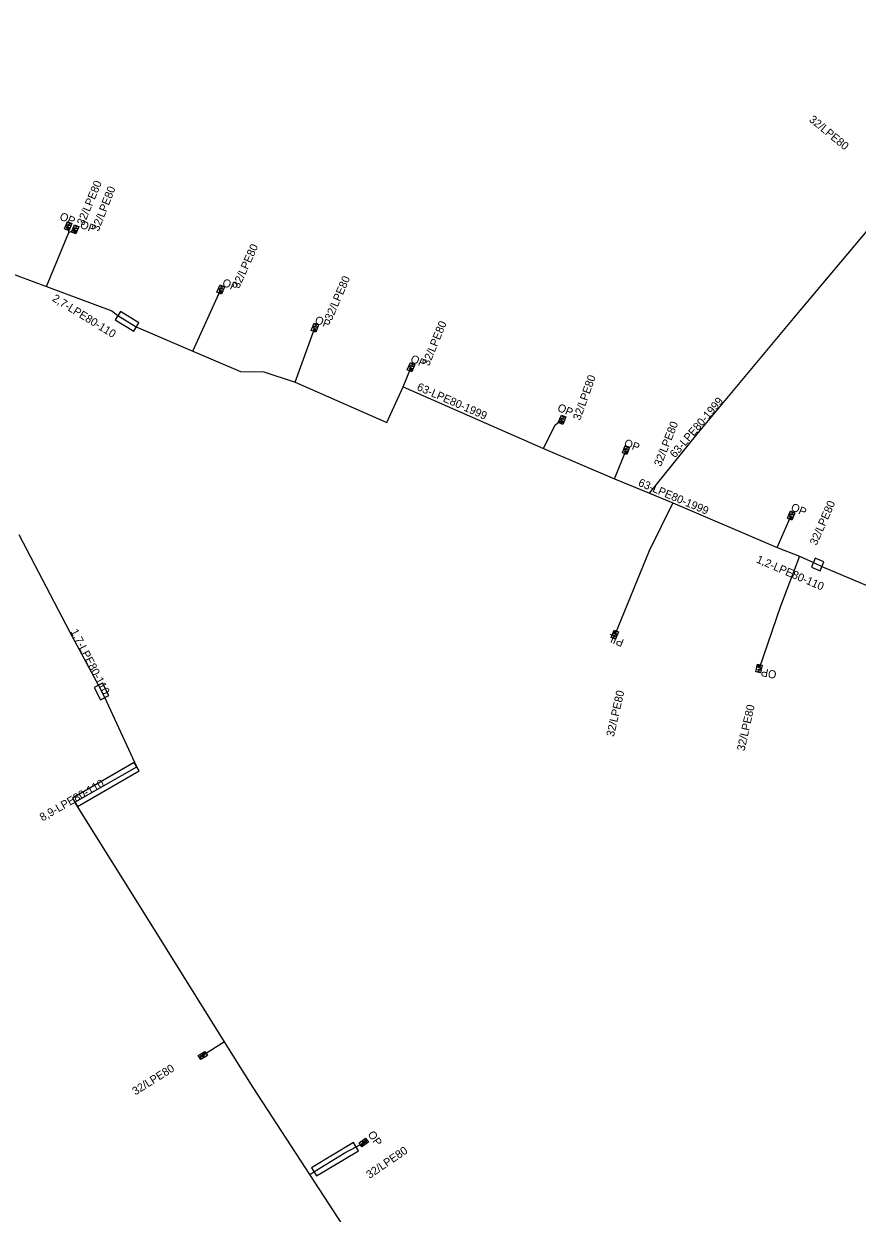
# Model space of a CAD drawing. Extents: x -762509 to -761250, y -1153000 to -1152256.
# Drawn here: x -761661 to -761556.9, y -1152409.7 to -1152261.2 of the extents above; entities that cross this region are included whole.
import ezdxf

# ---------------------------------------------------------------- set-up
doc = ezdxf.new("R2010")
doc.units = 0
for name, color, linetype in [('Vrstva 21', 7, 'Continuous'), ('Vrstva 29', 7, 'Continuous'), ('Vrstva 31', 7, 'Continuous'), ('Vrstva 32', 7, 'Continuous')]:
    doc.layers.add(name, color=color, linetype=linetype)

msp = doc.modelspace()

# ---------------------------------------------------------------- linework, layer by layer
at = {"layer": 'Vrstva 21'}
for points in [[(-761582.89, -1152319.81), (-761576.95, -1152312.47), (-761564.9, -1152298), (-761554.61, -1152285.76), (-761550.95, -1152281.56), (-761549.55, -1152279.71), (-761545.49, -1152275.05), (-761544.72, -1152274.11), (-761543.9, -1152273.16), (-761542.29, -1152270.99), (-761534.6, -1152261.85), (-761533.98, -1152261.17)], [(-761673.77, -1152305.98), (-761670.38, -1152302.71), (-761665.53, -1152296.98), (-761663.56, -1152291.99), (-761658.21, -1152293.99), (-761650.05, -1152297.02), (-761649.29, -1152297.62), (-761646.99, -1152299.04), (-761639.92, -1152302.07), (-761633.99, -1152304.61), (-761631.07, -1152304.65), (-761627.14, -1152305.92), (-761615.71, -1152310.97), (-761613.66, -1152306.5), (-761596.11, -1152314.22), (-761587.24, -1152318.01), (-761582.89, -1152319.81)], [(-761582.89, -1152319.81), (-761579.97, -1152321.01), (-761566.93, -1152326.59), (-761564.15, -1152327.67), (-761562.41, -1152328.48), (-761561.34, -1152328.94), (-761548.12, -1152334.52), (-761539.24, -1152337.93), (-761531.97, -1152340.58), (-761528.13, -1152341.92), (-761526.3, -1152342.45), (-761512.91, -1152346.54), (-761513.62, -1152349.91), (-761513.51, -1152352.59), (-761512.99, -1152352.67)], [(-761617.59, -1152416.73), (-761625.33, -1152404.89), (-761632.4, -1152394.03), (-761635.99, -1152388.35), (-761645.13, -1152373.62), (-761654.65, -1152358.4), (-761646.94, -1152353.98), (-761650.93, -1152345.33), (-761651.72, -1152343.79), (-761655.26, -1152337.2), (-761661.63, -1152325.02)]]:
    msp.add_lwpolyline(points, dxfattribs=at)
at = {"layer": 'Vrstva 29'}
for points in [[(-761649.61, -1152298.13), (-761647.31, -1152299.55), (-761646.67, -1152298.53), (-761648.97, -1152297.11)], [(-761562.65, -1152329.03), (-761561.58, -1152329.49), (-761561.1, -1152328.39), (-761562.17, -1152327.93)], [(-761652.25, -1152344.06), (-761651.46, -1152345.6), (-761650.4, -1152345.06), (-761651.19, -1152343.52)], [(-761654.35, -1152358.92), (-761646.64, -1152354.5), (-761647.24, -1152353.46), (-761654.95, -1152357.88)], [(-761624.49, -1152405.09), (-761619.23, -1152401.94), (-761619.85, -1152400.92), (-761625.11, -1152404.06)]]:
    msp.add_lwpolyline(points, close=True, dxfattribs=at)
at = {"layer": 'Vrstva 31'}
for points in [[(-761655.41, -1152287.23), (-761655.49, -1152286.45)], [(-761658.21, -1152293.99), (-761655.41, -1152287.24)], [(-761655.41, -1152287.24), (-761654.63, -1152286.85)], [(-761639.92, -1152302.07), (-761639.5, -1152301.15), (-761636.44, -1152294.37)], [(-761627.14, -1152305.92), (-761624.68, -1152299.13)], [(-761613.66, -1152306.5), (-761612.66, -1152304.06)], [(-761596.11, -1152314.22), (-761594.65, -1152311.27), (-761593.8, -1152310.63)], [(-761587.24, -1152318.01), (-761585.81, -1152314.41)], [(-761579.97, -1152321.01), (-761582.94, -1152327.01), (-761587.2, -1152337.48)], [(-761566.93, -1152326.59), (-761565.18, -1152322.59)], [(-761564.15, -1152327.67), (-761566.53, -1152333.91), (-761569.19, -1152341.7)], [(-761635.99, -1152388.35), (-761638.68, -1152390.04)], [(-761625.33, -1152404.89), (-761624.8, -1152404.58), (-761621.04, -1152402.25), (-761619.54, -1152401.43), (-761618.57, -1152400.92)]]:
    msp.add_lwpolyline(points, dxfattribs=at)
at = {"layer": 'Vrstva 32'}
for p, q in [((-761655.729, -1152286.567), (-761655.406, -1152286.703)), ((-761655.574, -1152286.199), (-761655.252, -1152286.335)), ((-761655.174, -1152286.149), (-761655.497, -1152286.014)), ((-761655.326, -1152286.085), (-761655.404, -1152286.271)), ((-761654.721, -1152286.601), (-761654.395, -1152286.729)), ((-761654.321, -1152286.542), (-761654.647, -1152286.414)), ((-761654.475, -1152286.482), (-761654.548, -1152286.669)), ((-761654.866, -1152286.973), (-761654.54, -1152287.101)), ((-761636.122, -1152294.07), (-761636.445, -1152293.933)), ((-761636.274, -1152294.005), (-761636.353, -1152294.19)), ((-761636.679, -1152294.485), (-761636.357, -1152294.622)), ((-761636.523, -1152294.118), (-761636.201, -1152294.255)), ((-761624.914, -1152299.257), (-761624.586, -1152299.379)), ((-761624.774, -1152298.883), (-761624.446, -1152299.005)), ((-761624.376, -1152298.817), (-761624.704, -1152298.695)), ((-761624.531, -1152298.759), (-761624.601, -1152298.947)), ((-761612.901, -1152304.173), (-761612.58, -1152304.314)), ((-761612.74, -1152303.808), (-761612.419, -1152303.949)), ((-761612.338, -1152303.765), (-761612.659, -1152303.624)), ((-761612.489, -1152303.698), (-761612.57, -1152303.882)), ((-761593.885, -1152310.379), (-761593.562, -1152310.513)), ((-761593.485, -1152310.328), (-761593.808, -1152310.193)), ((-761593.637, -1152310.264), (-761593.714, -1152310.45)), ((-761594.038, -1152310.748), (-761593.715, -1152310.882)), ((-761586.043, -1152314.538), (-761585.715, -1152314.658)), ((-761585.906, -1152314.163), (-761585.577, -1152314.284)), ((-761585.508, -1152314.095), (-761585.837, -1152313.975)), ((-761585.663, -1152314.038), (-761585.732, -1152314.227)), ((-761565.262, -1152322.337), (-761564.941, -1152322.477)), ((-761564.86, -1152322.293), (-761565.181, -1152322.153)), ((-761565.012, -1152322.227), (-761565.092, -1152322.411)), ((-761565.421, -1152322.703), (-761565.1, -1152322.843)), ((-761587.513, -1152337.785), (-761587.189, -1152337.917)), ((-761587.113, -1152337.731), (-761587.438, -1152337.599)), ((-761587.361, -1152337.847), (-761587.285, -1152337.661)), ((-761586.963, -1152337.361), (-761587.287, -1152337.229)), ((-761568.978, -1152341.539), (-761569.321, -1152341.469)), ((-761569.441, -1152342.057), (-761569.098, -1152342.127)), ((-761569.058, -1152341.93), (-761569.401, -1152341.86)), ((-761569.28, -1152342.09), (-761569.239, -1152341.893)), ((-761639.112, -1152390.104), (-761638.926, -1152390.401)), ((-761639.024, -1152390.244), (-761638.854, -1152390.137)), ((-761638.755, -1152390.294), (-761638.942, -1152389.997)), ((-761638.418, -1152390.081), (-761638.604, -1152389.785)), ((-761618.834, -1152400.894), (-761618.631, -1152401.179)), ((-761618.509, -1152400.662), (-761618.306, -1152400.947)), ((-761618.238, -1152400.696), (-761618.402, -1152400.813)), ((-761618.142, -1152400.83), (-761618.346, -1152400.545))]:
    msp.add_line(p, q, dxfattribs=at)
for points in [[(-761655.02, -1152286.105), (-761655.407, -1152287.028), (-761655.96, -1152286.795), (-761655.573, -1152285.873), (-761655.02, -1152286.105)], [(-761655.29, -1152286.426), (-761655.521, -1152286.329), (-761655.572, -1152286.323), (-761655.614, -1152286.339), (-761655.646, -1152286.371), (-761655.657, -1152286.397), (-761655.658, -1152286.443), (-761655.639, -1152286.482), (-761655.599, -1152286.514), (-761655.368, -1152286.611)], [(-761655.406, -1152286.703), (-761655.456, -1152286.822), (-761655.488, -1152286.855), (-761655.509, -1152286.862), (-761655.545, -1152286.862), (-761655.591, -1152286.843), (-761655.616, -1152286.817), (-761655.625, -1152286.797), (-761655.624, -1152286.752), (-761655.574, -1152286.632)], [(-761654.168, -1152286.495), (-761654.534, -1152287.425), (-761655.092, -1152287.206), (-761654.727, -1152286.275), (-761654.168, -1152286.495)], [(-761654.431, -1152286.821), (-761654.665, -1152286.73), (-761654.715, -1152286.725), (-761654.757, -1152286.742), (-761654.788, -1152286.774), (-761654.799, -1152286.801), (-761654.799, -1152286.847), (-761654.778, -1152286.886), (-761654.738, -1152286.917), (-761654.504, -1152287.008)], [(-761654.54, -1152287.101), (-761654.588, -1152287.222), (-761654.619, -1152287.254), (-761654.639, -1152287.263), (-761654.675, -1152287.264), (-761654.722, -1152287.245), (-761654.747, -1152287.22), (-761654.757, -1152287.2), (-761654.757, -1152287.155), (-761654.71, -1152287.034)], [(-761635.968, -1152294.026), (-761636.359, -1152294.947), (-761636.911, -1152294.713), (-761636.521, -1152293.792), (-761635.968, -1152294.026)], [(-761636.24, -1152294.346), (-761636.471, -1152294.248), (-761636.521, -1152294.242), (-761636.564, -1152294.257), (-761636.596, -1152294.289), (-761636.607, -1152294.316), (-761636.608, -1152294.361), (-761636.589, -1152294.401), (-761636.549, -1152294.433), (-761636.318, -1152294.531)], [(-761636.357, -1152294.622), (-761636.407, -1152294.742), (-761636.439, -1152294.774), (-761636.46, -1152294.781), (-761636.496, -1152294.781), (-761636.542, -1152294.762), (-761636.567, -1152294.736), (-761636.576, -1152294.716), (-761636.575, -1152294.671), (-761636.524, -1152294.551)], [(-761624.224, -1152298.767), (-761624.573, -1152299.704), (-761625.136, -1152299.494), (-761624.786, -1152298.557), (-761624.224, -1152298.767)], [(-761624.481, -1152299.098), (-761624.716, -1152299.01), (-761624.767, -1152299.006), (-761624.809, -1152299.024), (-761624.839, -1152299.057), (-761624.85, -1152299.084), (-761624.848, -1152299.13), (-761624.827, -1152299.168), (-761624.786, -1152299.199), (-761624.551, -1152299.286)], [(-761624.586, -1152299.379), (-761624.631, -1152299.501), (-761624.662, -1152299.534), (-761624.682, -1152299.543), (-761624.718, -1152299.544), (-761624.765, -1152299.527), (-761624.791, -1152299.502), (-761624.8, -1152299.483), (-761624.802, -1152299.437), (-761624.756, -1152299.315)], [(-761612.184, -1152303.724), (-761612.587, -1152304.639), (-761613.136, -1152304.397), (-761612.733, -1152303.482), (-761612.184, -1152303.724)], [(-761612.459, -1152304.039), (-761612.689, -1152303.938), (-761612.74, -1152303.931), (-761612.782, -1152303.946), (-761612.815, -1152303.978), (-761612.826, -1152304.004), (-761612.828, -1152304.05), (-761612.809, -1152304.089), (-761612.77, -1152304.122), (-761612.54, -1152304.223)], [(-761612.58, -1152304.314), (-761612.633, -1152304.433), (-761612.665, -1152304.464), (-761612.686, -1152304.472), (-761612.722, -1152304.471), (-761612.768, -1152304.451), (-761612.792, -1152304.425), (-761612.801, -1152304.405), (-761612.799, -1152304.359), (-761612.747, -1152304.24)], [(-761593.331, -1152310.283), (-761593.714, -1152311.207), (-761594.268, -1152310.977), (-761593.885, -1152310.053), (-761593.331, -1152310.283)], [(-761593.6, -1152310.605), (-761593.832, -1152310.509), (-761593.882, -1152310.503), (-761593.925, -1152310.519), (-761593.956, -1152310.551), (-761593.968, -1152310.578), (-761593.968, -1152310.623), (-761593.949, -1152310.662), (-761593.909, -1152310.694), (-761593.677, -1152310.79)], [(-761593.715, -1152310.882), (-761593.765, -1152311.002), (-761593.796, -1152311.034), (-761593.817, -1152311.042), (-761593.853, -1152311.042), (-761593.899, -1152311.023), (-761593.924, -1152310.997), (-761593.933, -1152310.977), (-761593.933, -1152310.932), (-761593.883, -1152310.812)], [(-761585.357, -1152314.044), (-761585.7, -1152314.983), (-761586.264, -1152314.777), (-761585.92, -1152313.838), (-761585.357, -1152314.044)], [(-761585.612, -1152314.377), (-761585.847, -1152314.29), (-761585.898, -1152314.287), (-761585.94, -1152314.305), (-761585.97, -1152314.338), (-761585.98, -1152314.365), (-761585.979, -1152314.411), (-761585.958, -1152314.449), (-761585.916, -1152314.479), (-761585.681, -1152314.566)], [(-761585.715, -1152314.658), (-761585.759, -1152314.781), (-761585.79, -1152314.814), (-761585.81, -1152314.823), (-761585.846, -1152314.825), (-761585.893, -1152314.807), (-761585.919, -1152314.783), (-761585.929, -1152314.763), (-761585.93, -1152314.718), (-761585.886, -1152314.596)], [(-761564.706, -1152322.251), (-761565.105, -1152323.168), (-761565.655, -1152322.929), (-761565.256, -1152322.012), (-761564.706, -1152322.251)], [(-761564.98, -1152322.568), (-761565.21, -1152322.468), (-761565.261, -1152322.461), (-761565.303, -1152322.476), (-761565.336, -1152322.508), (-761565.347, -1152322.535), (-761565.348, -1152322.58), (-761565.33, -1152322.62), (-761565.29, -1152322.652), (-761565.06, -1152322.752)], [(-761565.1, -1152322.843), (-761565.152, -1152322.962), (-761565.184, -1152322.994), (-761565.205, -1152323.001), (-761565.241, -1152323.001), (-761565.286, -1152322.981), (-761565.311, -1152322.955), (-761565.32, -1152322.935), (-761565.319, -1152322.89), (-761565.267, -1152322.77)], [(-761587.667, -1152337.83), (-761587.29, -1152336.904), (-761586.734, -1152337.13), (-761587.111, -1152338.056), (-761587.667, -1152337.83)], [(-761587.287, -1152337.229), (-761587.238, -1152337.109), (-761587.207, -1152337.076), (-761587.186, -1152337.068), (-761587.15, -1152337.068), (-761587.104, -1152337.087), (-761587.079, -1152337.112), (-761587.07, -1152337.132), (-761587.07, -1152337.177), (-761587.119, -1152337.298)], [(-761587.4, -1152337.507), (-761587.168, -1152337.602), (-761587.117, -1152337.607), (-761587.075, -1152337.591), (-761587.043, -1152337.558), (-761587.032, -1152337.531), (-761587.032, -1152337.486), (-761587.052, -1152337.447), (-761587.092, -1152337.415), (-761587.325, -1152337.321)], [(-761569.584, -1152342.13), (-761569.384, -1152341.15), (-761568.796, -1152341.27), (-761568.996, -1152342.25), (-761569.584, -1152342.13)], [(-761569.381, -1152341.763), (-761569.135, -1152341.813), (-761569.085, -1152341.809), (-761569.046, -1152341.786), (-761569.021, -1152341.748), (-761569.015, -1152341.719), (-761569.023, -1152341.675), (-761569.05, -1152341.64), (-761569.095, -1152341.616), (-761569.341, -1152341.566)], [(-761569.321, -1152341.469), (-761569.295, -1152341.342), (-761569.27, -1152341.304), (-761569.252, -1152341.293), (-761569.217, -1152341.285), (-761569.168, -1152341.295), (-761569.138, -1152341.316), (-761569.125, -1152341.334), (-761569.117, -1152341.378), (-761569.143, -1152341.506)], [(-761639.263, -1152390.052), (-761638.416, -1152389.52), (-761638.097, -1152390.028), (-761638.944, -1152390.56), (-761639.263, -1152390.052)], [(-761638.858, -1152389.945), (-761638.724, -1152390.157), (-761638.686, -1152390.191), (-761638.642, -1152390.203), (-761638.598, -1152390.195), (-761638.573, -1152390.179), (-761638.547, -1152390.143), (-761638.54, -1152390.099), (-761638.554, -1152390.05), (-761638.688, -1152389.838)], [(-761638.604, -1152389.785), (-761638.494, -1152389.716), (-761638.449, -1152389.708), (-761638.428, -1152389.714), (-761638.398, -1152389.734), (-761638.372, -1152389.776), (-761638.366, -1152389.812), (-761638.37, -1152389.833), (-761638.397, -1152389.87), (-761638.507, -1152389.939)], [(-761617.988, -1152400.874), (-761618.802, -1152401.455), (-761619.151, -1152400.967), (-761618.337, -1152400.385), (-761617.988, -1152400.874)], [(-761618.631, -1152401.179), (-761618.736, -1152401.254), (-761618.78, -1152401.265), (-761618.802, -1152401.261), (-761618.833, -1152401.242), (-761618.862, -1152401.201), (-761618.869, -1152401.166), (-761618.867, -1152401.144), (-761618.842, -1152401.106), (-761618.736, -1152401.031)], [(-761618.386, -1152401.004), (-761618.532, -1152400.8), (-761618.572, -1152400.768), (-761618.617, -1152400.76), (-761618.661, -1152400.77), (-761618.684, -1152400.787), (-761618.709, -1152400.825), (-761618.713, -1152400.869), (-761618.696, -1152400.917), (-761618.55, -1152401.121)]]:
    msp.add_lwpolyline(points, dxfattribs=at)

# ---------------------------------------------------------------- texts
at = {"layer": 'Vrstva 21'}
for rotation, p in [(336.25597, (-761612.02, -1152306.88)), (49.41426, (-761579.69, -1152315.46)), (336.8939, (-761584.37, -1152318.84))]:
    msp.add_text('63-LPE80-1999', height=1, rotation=rotation, dxfattribs=at).set_placement(p)
at = {"layer": 'Vrstva 29'}
for s, rotation, p in [('2,7-LPE80-110', 328.30918, (-761657.58, -1152295.72)), ('1,2-LPE80-110', 336.73681, (-761569.62, -1152328.43)), ('1,7-LPE80-110', 297.15723, (-761655.24, -1152337.06)), ('8,9-LPE80-110', 29.82485, (-761658.71, -1152360.81))]:
    msp.add_text(s, height=1, rotation=rotation, dxfattribs=at).set_placement(p)
at = {"layer": 'Vrstva 31'}
for rotation, p in [(320.44865, (-761563.03, -1152273.28)), (320.44865, (-761563.03, -1152273.28)), (67.32193, (-761653.54, -1152286.43)), (67.32193, (-761653.54, -1152286.43)), (68.62732, (-761651.7, -1152287.17)), (68.62732, (-761651.7, -1152287.17)), (65.70904, (-761634.15, -1152294.31)), (65.70904, (-761634.15, -1152294.31)), (66.48821, (-761622.59, -1152298.32)), (66.48821, (-761622.59, -1152298.32)), (67.71441, (-761610.42, -1152303.98)), (67.71441, (-761610.42, -1152303.98)), (70.41499, (-761591.54, -1152310.78)), (70.41499, (-761591.54, -1152310.78)), (68.33593, (-761581.44, -1152316.54)), (68.33593, (-761581.44, -1152316.54)), (66.37062, (-761562, -1152326.39)), (66.37062, (-761562, -1152326.39)), (77.0475, (-761587.33, -1152350.29)), (77.0475, (-761587.33, -1152350.29)), (77.26462, (-761571.02, -1152352.07)), (77.26462, (-761571.02, -1152352.07)), (32.13921, (-761647.1, -1152395.03)), (32.13921, (-761647.1, -1152395.03)), (34.36363, (-761617.84, -1152405.46)), (34.36363, (-761617.84, -1152405.46))]:
    msp.add_text('32/LPE80', height=1, rotation=rotation, dxfattribs=at).set_placement(p)
at = {"layer": 'Vrstva 32'}
for s, rotation, p in [('OP', 337.23488, (-761656.66, -1152285.59)), ('OP', 337.23488, (-761656.66, -1152285.59)), ('OP', 338.58049, (-761654.11, -1152286.62)), ('OP', 338.58049, (-761654.11, -1152286.62)), ('OP', 337.02579, (-761636.34, -1152293.86)), ('OP', 337.02579, (-761636.34, -1152293.86)), ('OP', 339.56399, (-761624.77, -1152298.55)), ('OP', 339.56399, (-761624.77, -1152298.55)), ('OP', 336.21845, (-761612.83, -1152303.37)), ('OP', 336.21845, (-761612.83, -1152303.37)), ('OP', 337.48116, (-761594.47, -1152309.49)), ('OP', 337.48116, (-761594.47, -1152309.49)), ('OP', 339.88452, (-761586.14, -1152313.93)), ('OP', 339.88452, (-761586.14, -1152313.93)), ('OP', 336.48442, (-761565.31, -1152321.91)), ('OP', 336.48442, (-761565.31, -1152321.91)), ('PIL', 157.85973, (-761585.99, -1152338.11)), ('PIL', 157.85973, (-761585.99, -1152338.11)), ('OP', 168.48031, (-761566.94, -1152342.03)), ('OP', 168.48031, (-761566.94, -1152342.03)), ('OP', 305.52967, (-761618.14, -1152399.89)), ('OP', 305.52967, (-761618.14, -1152399.89))]:
    msp.add_text(s, height=1, rotation=rotation, dxfattribs=at).set_placement(p)

doc.saveas('drawing.dxf')
